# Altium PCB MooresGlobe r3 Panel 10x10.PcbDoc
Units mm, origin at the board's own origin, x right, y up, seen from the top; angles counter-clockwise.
Board outline 120 x 130 mm, 2 copper layers (Top Layer, Bottom Layer); 0 components, 0 nets, 23 pads, 0 vias.
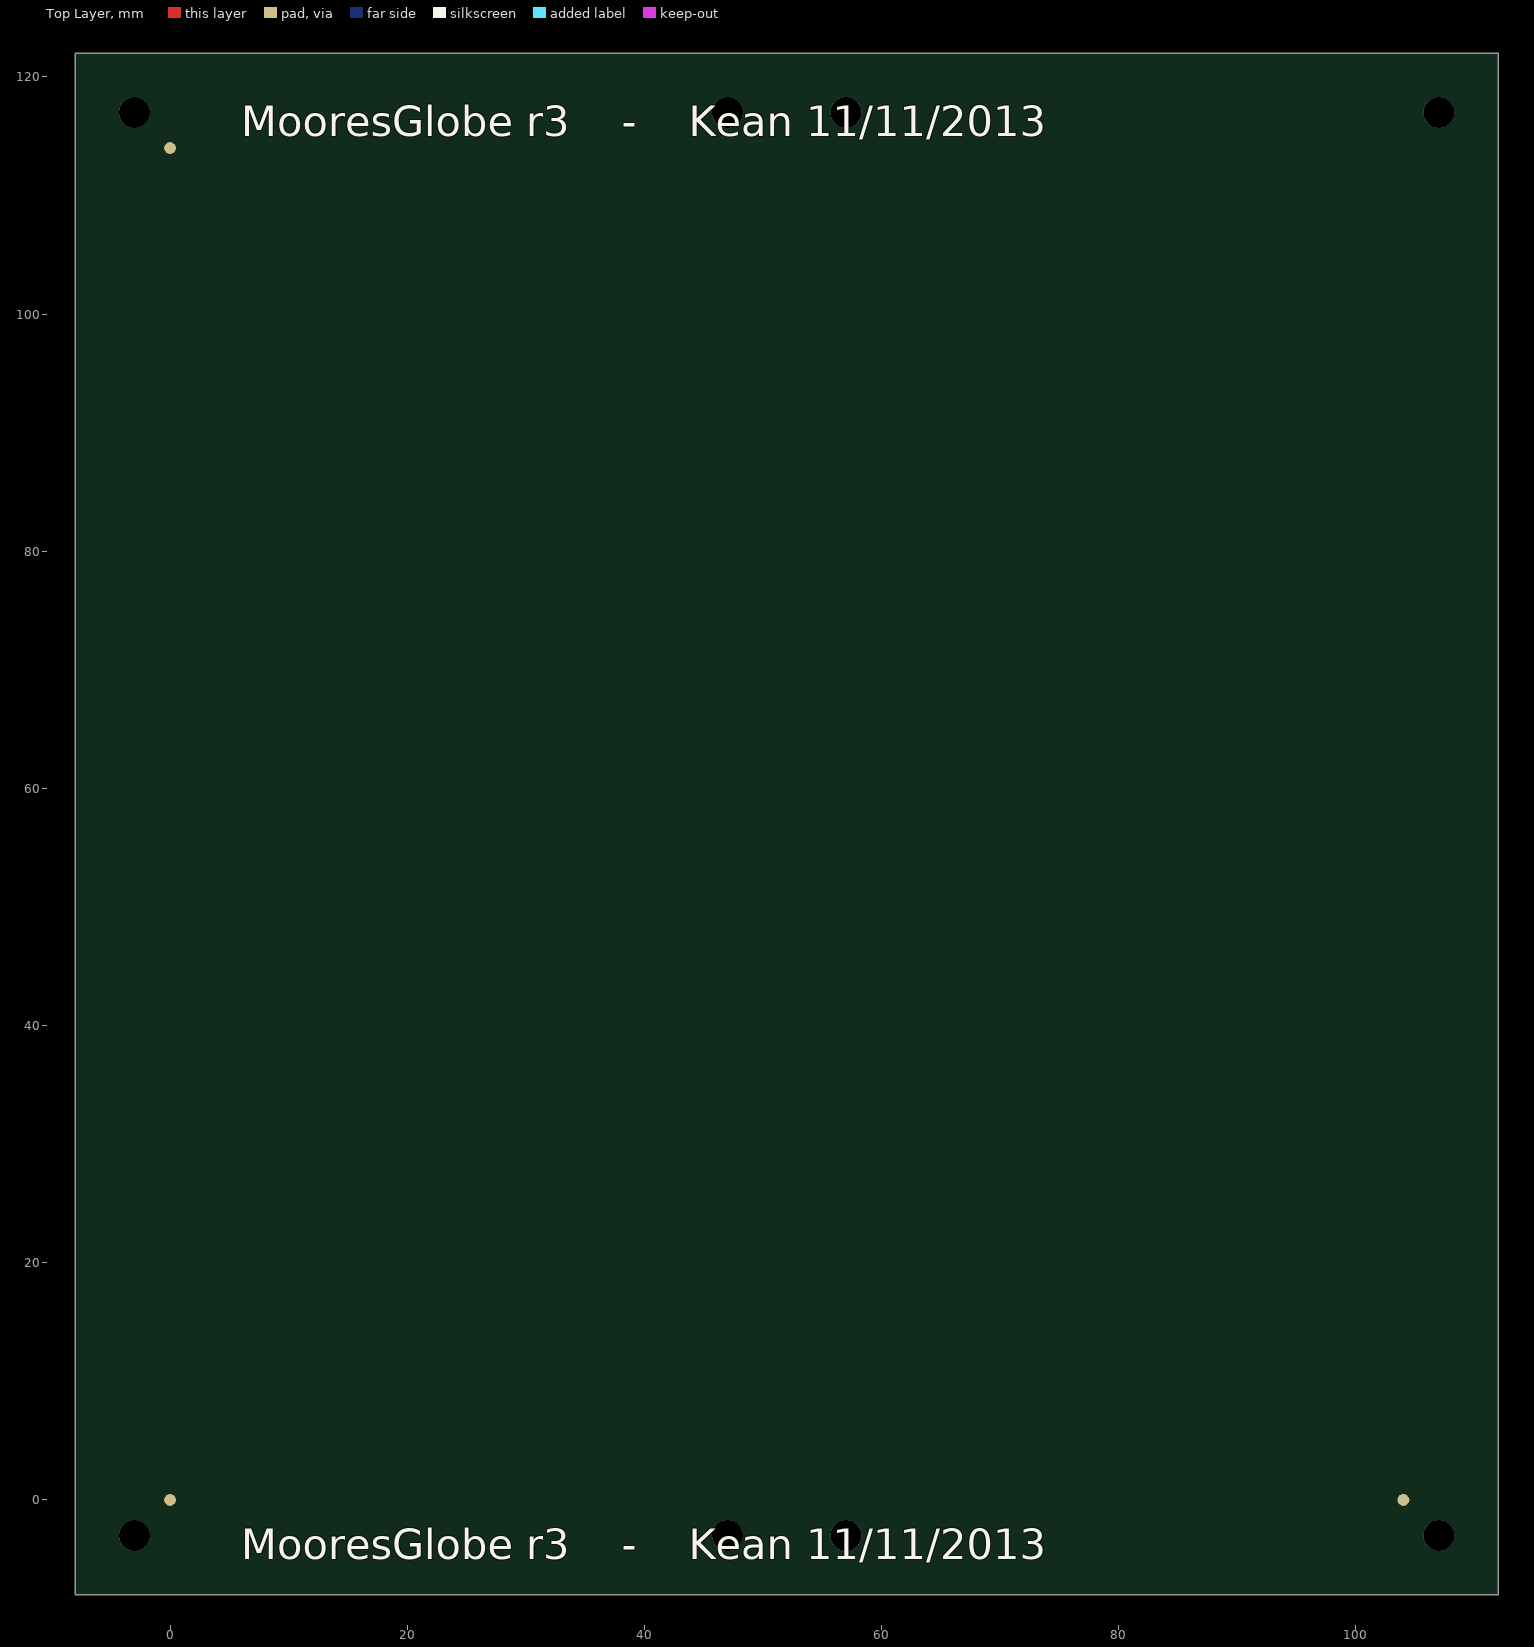
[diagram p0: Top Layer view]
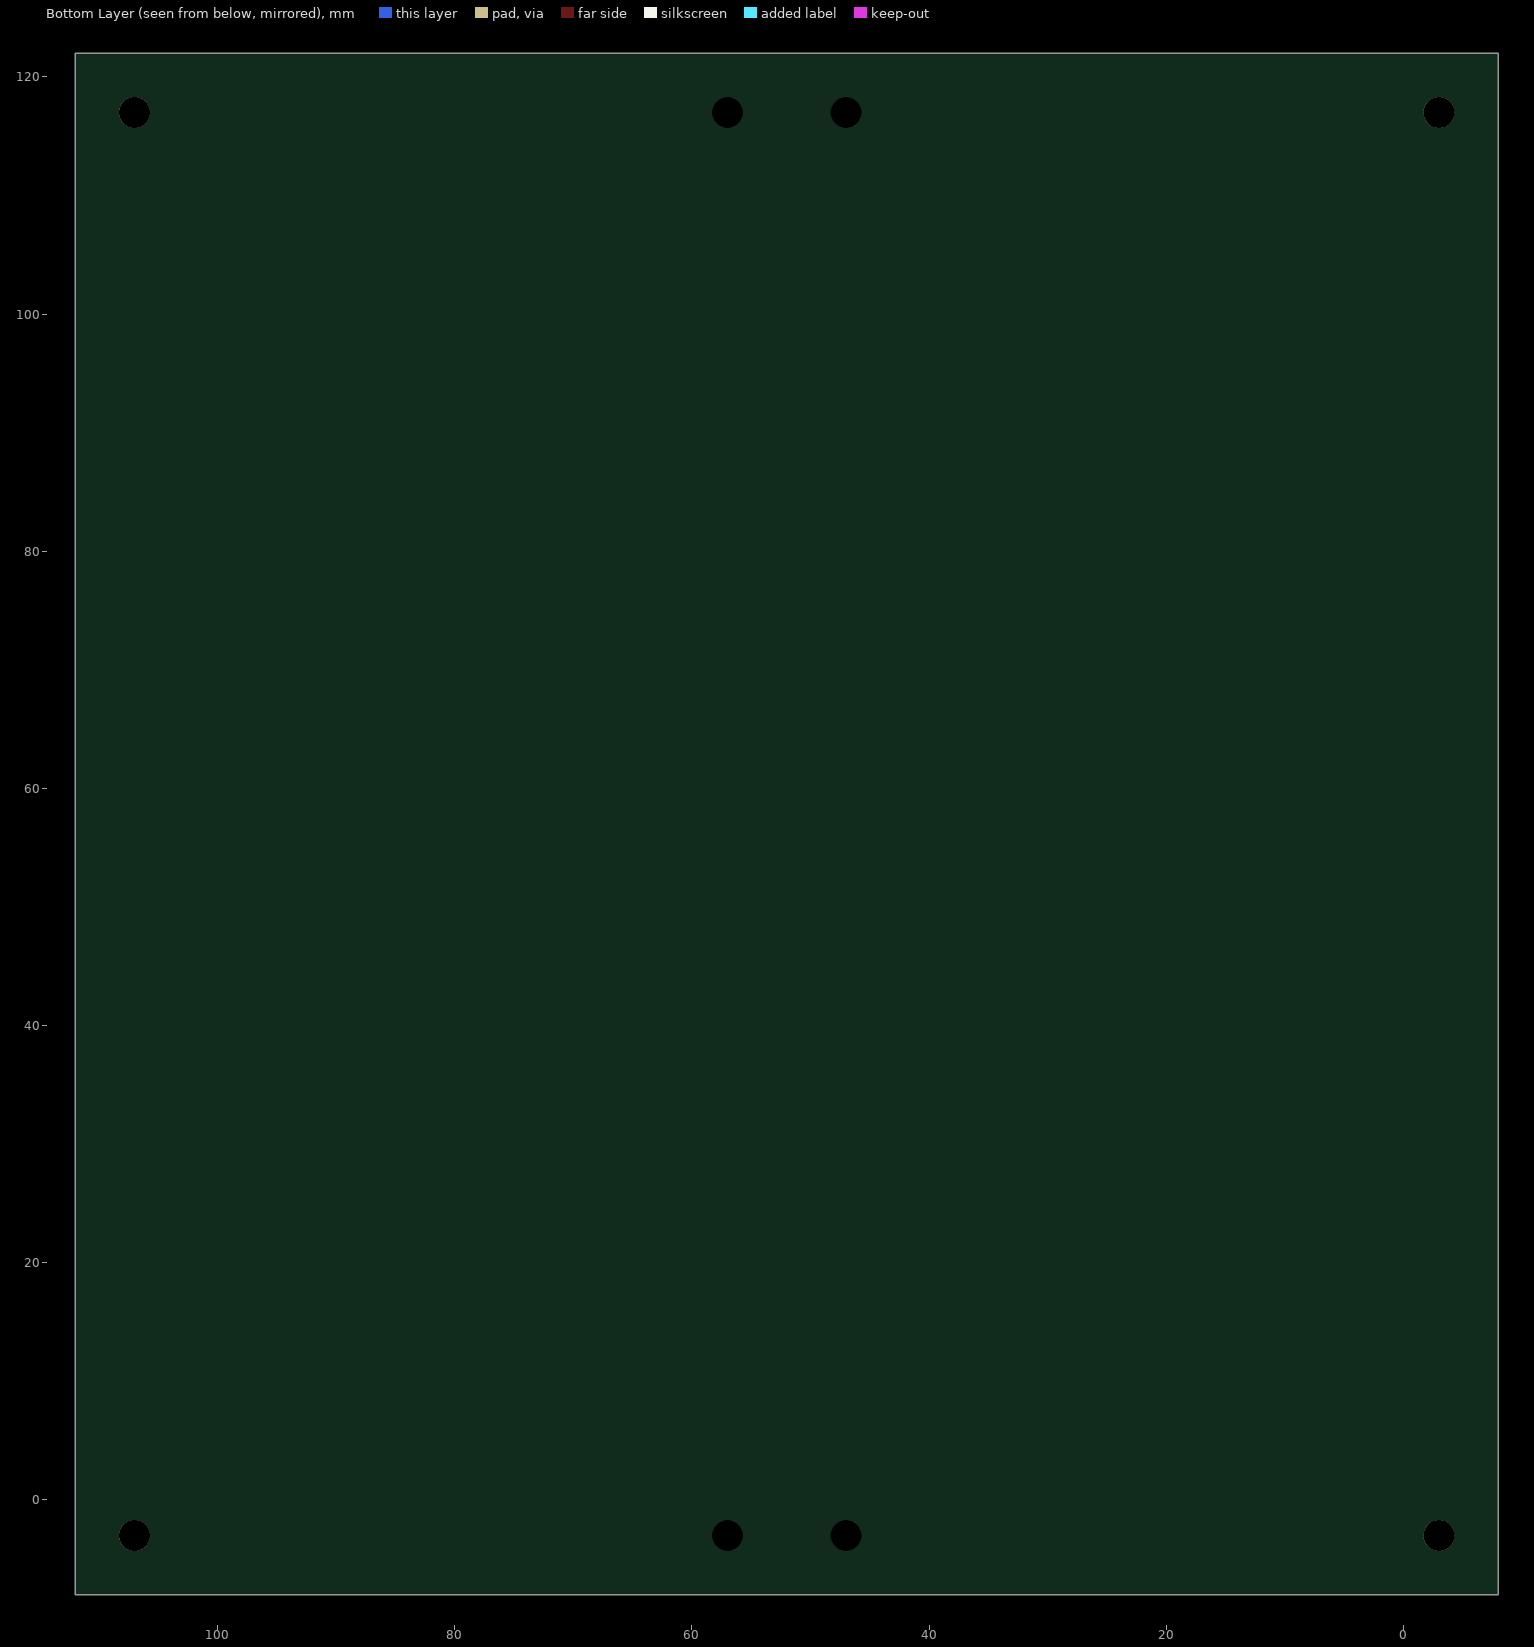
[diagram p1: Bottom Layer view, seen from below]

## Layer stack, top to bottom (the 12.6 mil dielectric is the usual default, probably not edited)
Top Layer: signal copper 0.0356
Dielectric: core 0.32, FR-4, Dk 4.8
Bottom Layer: signal copper 0.0356

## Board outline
-8,-8 112,-8 112,122 -8,122

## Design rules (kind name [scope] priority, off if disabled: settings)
Clearance [All] p1: gap=0.254
PolygonConnect [All] p1: connectstyle=Relief reliefconductorwidth=0.254 reliefentries=4 polygonreliefangle="90 Angle" airgapwidth=0.254
RoutingVias [All] p1: holewidth=0.711 width=1.27 viastyle="Through Hole" minholewidth=0.711 minwidth=1.27 maxholewidth=0.711 maxwidth=1.27
SolderMaskExpansion [All] p1: expansion=0.102
Width [All] p1: maxlimit=0.254 minlimit=0.254 preferedwidth=0.254
28 further rules are at their usual default settings.

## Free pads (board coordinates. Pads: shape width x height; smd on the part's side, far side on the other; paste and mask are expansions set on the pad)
  round 0 hole 2.6 unplated: 0(-3,-3) 0(-3,117) 0(47,-3) 0(47,117) 0(57,-3) 0(57,117) 0(107,-3) 0(107,117)
  round 2.6 smd paste-3 mask+0: 0(-3,-3) 0(-3,117) 0(47,-3) 0(47,117) 0(57,-3) 0(57,117) 0(107,-3) 0(107,117)
  round 2.6 smd far side paste-3 mask+0: 0(-3,-3) 0(-3,117) 0(107,-3) 0(107,117)
  round 1 smd paste-1 mask+1: FID1(0,0) FID2(0,114) FID3(104,0)

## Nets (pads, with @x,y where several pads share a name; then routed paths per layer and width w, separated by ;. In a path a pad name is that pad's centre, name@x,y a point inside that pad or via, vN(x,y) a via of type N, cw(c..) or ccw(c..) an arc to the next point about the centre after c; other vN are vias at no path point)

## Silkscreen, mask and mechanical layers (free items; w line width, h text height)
Top Overlay:
  text "MooresGlobe r3    -    Kean 11/11/2013" at 6,115 h2.54
  text "MooresGlobe r3    -    Kean 11/11/2013" at 6,-5 h2.54
Mechanical 2:
  text "Top Layer Component Keep Out Areas" at 143.9,20.2 h1
Mechanical 3:
  text "Bottom Layer Component Keep Out Areas" at 143.9,18.2 h1
Mechanical 5:
  lines w0.1: 143.9,12.95 202.15,12.95 ; 143.9,14.95 202.15,14.95 ; 143.9,23.7 202.15,23.7 ; 143.9,25.7 202.15,25.7 ; 143.9,27.7 202.15,27.7 ; 143.9,29.7 202.15,29.7 ; 143.9,31.7 202.15,31.7 ; 143.9,33.7 202.15,33.7 ; 143.9,35.7 202.15,35.7 ; 143.9,37.7 202.15,37.7 ; 156.3,43.6 156.3,45.6 ; 156.4,10.95 156.4,17.2 ; 156.4,21.7 156.4,39.7 ; 143.8,43.6 143.8,45.6 202.05,45.6 202.05,43.6 143.8,43.6 ; 143.9,10.95 143.9,17.2 202.15,17.2 202.15,10.95 143.9,10.95 ; 143.9,21.7 202.15,21.7 202.15,39.7 143.9,39.7 143.9,21.7
  lines w0.2: -8,2 112,2 ; -8,13 112,13 ; -8,24 112,24 ; -8,35 112,35 ; -8,46 112,46 ; -8,57 112,57 ; -8,68 112,68 ; -8,79 112,79 ; -8,90 112,90 ; -8,101 112,101 ; -8,112 112,112 ; 4,-8 4,122 ; 16,-8 16,122 ; 28,-8 28,122 ; 40,-8 40,122 ; 52,-8 52,122 ; 64,-8 64,122 ; 76,-8 76,122 ; 88,-8 88,122 ; 100,-8 100,122 ; -8,-8 112,-8 112,122 -8,122 -8,-8
  text "TOOL STRIP:" at 144.3,44.1 h1
  text "2.6mm HOLES x 8" at 157.3,44.1 h1
  text "BOARD SIZE:" at 144.4,38.2 h1
  text "120.00mm x 130.00mm" at 157.4,38.2 h1
  text "LAYERS:" at 144.4,36.2 h1
  text "2" at 157.4,36.2 h1
  text "MATERIAL:" at 144.4,34.2 h1
  text "FR4 0.8mm" at 157.4,34.2 h1
  text "COPPER:" at 144.4,32.2 h1
  text "35um (after plating)" at 157.4,32.2 h1
  text "PTH PLATING:" at 144.4,30.2 h1
  text "20um (minimum)" at 157.4,30.2 h1
  text "FINISH:" at 144.4,28.2 h1
  text "ROHS HAL" at 157.4,28.2 h1
  text "OVERLAY:" at 144.4,26.2 h1
  text "Black, 2 sides" at 157.4,26.2 h1
  text "SOLDER MASK:" at 144.4,24.2 h1
  text "White, 2 sides" at 157.4,24.2 h1
  text "PROFILING:" at 144.4,22.2 h1
  text "V-Groove" at 157.4,22.2 h1
  text "FILE NAME:" at 144.4,15.45 h1
  text ".Pcb_File_Name_No_Path" at 157.4,15.45 h1
  text "LAYER:" at 144.4,13.45 h1
  text ".Plot_File_Name" at 157.4,13.45 h1
  text "PRINT DATE:" at 144.4,11.45 h1
  text ".Print_Date" at 157.4,11.45 h1

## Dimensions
-8,2 to -8,13 on Mechanical 5
-8,-8 to -8,2 on Mechanical 5
100,124 to 100,132 on Mechanical 5
88,124 to 88,132 on Mechanical 5
76,124 to 76,132 on Mechanical 5
64,124 to 64,132 on Mechanical 5
52,124 to 52,132 on Mechanical 5
40,124 to 40,132 on Mechanical 5
28,124 to 28,132 on Mechanical 5
16,124 to 16,132 on Mechanical 5
-8,-8 to 112,-8 on Mechanical 5
-9,-8 to -8,122 on Mechanical 5
-3,-3 to -9,-8 on Mechanical 5
-8,-8 to 4,-9 on Mechanical 5
-3,-3 to -8,-8 on Mechanical 5
115,2 to 123,2 on Mechanical 5
115,13 to 123,13 on Mechanical 5
115,24 to 123,24 on Mechanical 5
115,35 to 123,35 on Mechanical 5
115,46 to 123,46 on Mechanical 5
115,57 to 123,57 on Mechanical 5
115,68 to 123,68 on Mechanical 5
115,79 to 123,79 on Mechanical 5
115,90 to 123,90 on Mechanical 5
115,101 to 123,101 on Mechanical 5
115,112 to 123,112 on Mechanical 5
4,124 to 4,132 on Mechanical 5

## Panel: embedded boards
"MooresGlobe r3.PcbDoc" at -8,2, 10 rows x 10 columns, spacing 11 x 12, rotation 0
